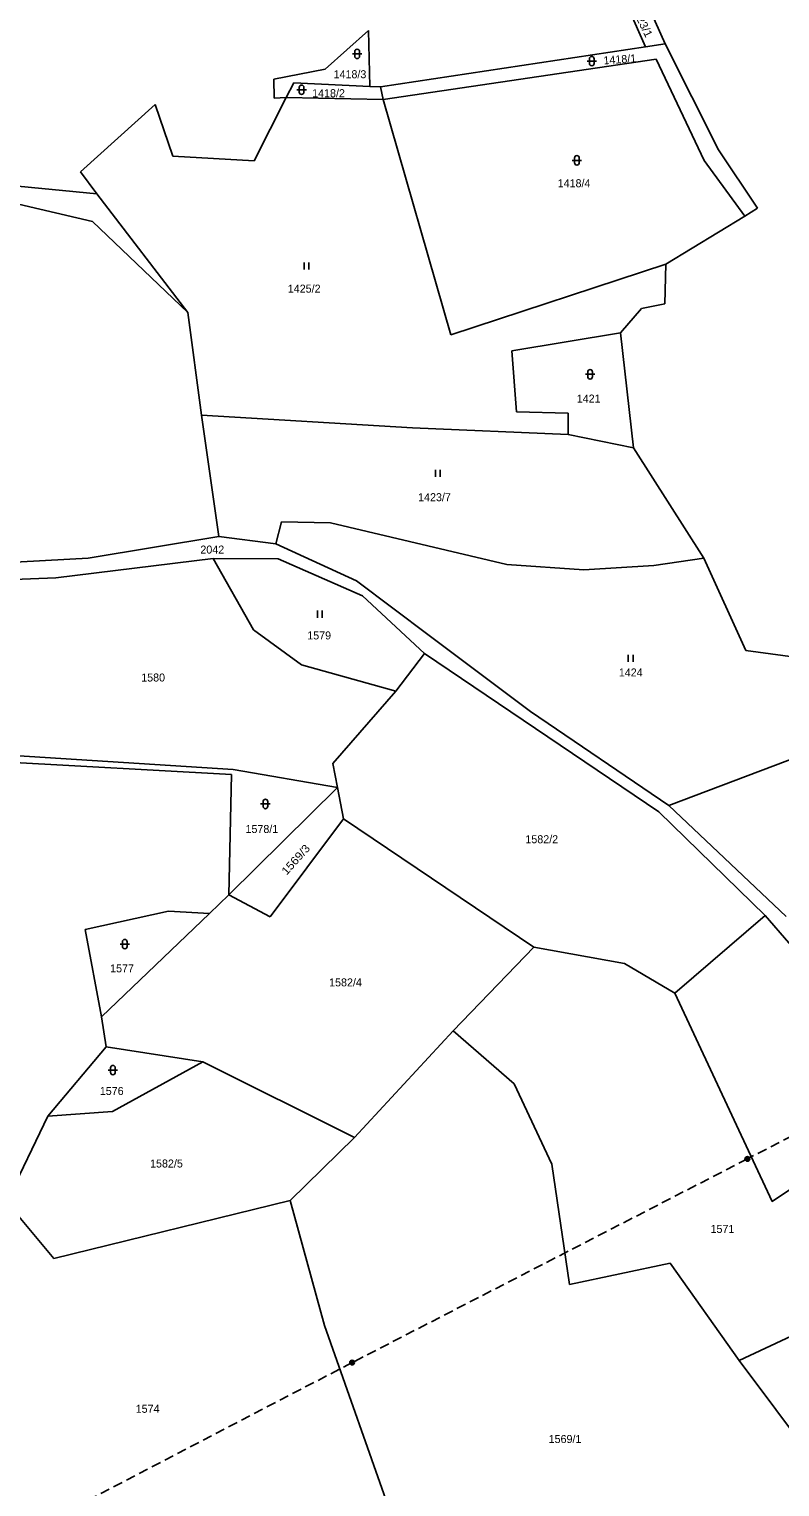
# Model space of a CAD drawing. Extents: x -820420 to -815896, y -1105820 to -1103643.
# Drawn here: x -819714.4 to -819555, y -1105122.1 to -1104812.4 of the extents above; entities that cross this region are included whole.
import ezdxf
from ezdxf.enums import TextEntityAlignment as Align

# ---------------------------------------------------------------- set-up
doc = ezdxf.new("R2010")
doc.units = 0
doc.header["$LTSCALE"] = 0.68
doc.linetypes.add('MEDIUM_DASHED', pattern=[4.5, 3, -1.5])
for name, color, linetype, lineweight in [('1', 7, 'Continuous', 25), ('3', 7, 'Continuous', 25), ('6', 7, 'Continuous', 25)]:
    doc.layers.add(name, color=color, linetype=linetype, lineweight=lineweight)
doc.layers.add('2', color=7, linetype='Continuous')

msp = doc.modelspace()

# ---------------------------------------------------------------- linework, layer by layer
at = {"layer": '1'}
for p, q in [((-819579.37, -1104815.59), (-819583.64, -1104806)), ((-819587.15, -1104808.04), (-819583.55, -1104816.2)), ((-819642.33, -1104812.74), (-819651.58, -1104820.92)), ((-819642.04, -1104824.65), (-819642.33, -1104812.74)), ((-819579.37, -1104815.59), (-819583.55, -1104816.2)), ((-819568.03, -1104838.09), (-819579.37, -1104815.59)), ((-819583.55, -1104816.2), (-819639.82, -1104824.69)), ((-819581.26, -1104818.83), (-819639.23, -1104827.35)), ((-819571.1, -1104840.38), (-819581.26, -1104818.83)), ((-819651.58, -1104820.92), (-819662.47, -1104823.07)), ((-819662.47, -1104823.07), (-819662.39, -1104827.12)), ((-819658.2, -1104823.82), (-819659.81, -1104826.98)), ((-819642.04, -1104824.65), (-819658.2, -1104823.82)), ((-819639.82, -1104824.69), (-819642.04, -1104824.65)), ((-819639.82, -1104824.69), (-819639.23, -1104827.35)), ((-819659.81, -1104826.98), (-819666.63, -1104840.44)), ((-819662.39, -1104827.12), (-819659.81, -1104826.98)), ((-819659.81, -1104826.98), (-819639.23, -1104827.35)), ((-819639.23, -1104827.35), (-819624.89, -1104877.35)), ((-819687.67, -1104828.45), (-819703.48, -1104842.74)), ((-819683.87, -1104839.45), (-819687.67, -1104828.45)), ((-819666.63, -1104840.44), (-819683.87, -1104839.45)), ((-819562.45, -1104852.17), (-819571.1, -1104840.38)), ((-819559.8, -1104850.47), (-819568.03, -1104838.09)), ((-819703.48, -1104842.74), (-819700.03, -1104847.45)), ((-819700.03, -1104847.45), (-819718.99, -1104845.59)), ((-819720, -1104848.84), (-819700.97, -1104853.31)), ((-819680.73, -1104872.66), (-819700.03, -1104847.45)), ((-819579.25, -1104862.38), (-819562.45, -1104852.17)), ((-819562.45, -1104852.17), (-819559.8, -1104850.47)), ((-819700.97, -1104853.31), (-819680.73, -1104872.66)), ((-819624.89, -1104877.35), (-819579.25, -1104862.38)), ((-819579.25, -1104862.38), (-819579.41, -1104870.8)), ((-819579.41, -1104870.8), (-819584.41, -1104871.8)), ((-819677.8, -1104894.43), (-819680.73, -1104872.66)), ((-819584.41, -1104871.8), (-819588.82, -1104876.95)), ((-819588.82, -1104876.95), (-819611.9, -1104880.79)), ((-819586.12, -1104901.36), (-819588.82, -1104876.95)), ((-819611.9, -1104880.79), (-819610.9, -1104893.76)), ((-819674.11, -1104920.23), (-819677.8, -1104894.43)), ((-819677.8, -1104894.43), (-819633.04, -1104897.15)), ((-819610.9, -1104893.76), (-819599.98, -1104894)), ((-819599.98, -1104894), (-819599.98, -1104898.54)), ((-819633.04, -1104897.15), (-819599.98, -1104898.54)), ((-819599.98, -1104898.54), (-819586.12, -1104901.36)), ((-819571.15, -1104924.83), (-819586.12, -1104901.36)), ((-819660.8, -1104917.11), (-819662.06, -1104921.79)), ((-819650.39, -1104917.34), (-819660.8, -1104917.11)), ((-819612.99, -1104926.2), (-819650.39, -1104917.34)), ((-819674.11, -1104920.23), (-819701.87, -1104924.82)), ((-819662.06, -1104921.79), (-819674.11, -1104920.23)), ((-819644.9, -1104929.62), (-819662.06, -1104921.79)), ((-819701.87, -1104924.82), (-819731.57, -1104926.45)), ((-819708.76, -1104928.99), (-819675.33, -1104924.89)), ((-819675.33, -1104924.89), (-819661.52, -1104925)), ((-819666.77, -1104940.09), (-819675.33, -1104924.89)), ((-819661.52, -1104925), (-819643.64, -1104932.8)), ((-819596.66, -1104927.28), (-819612.99, -1104926.2)), ((-819581.75, -1104926.4), (-819596.66, -1104927.28)), ((-819571.15, -1104924.83), (-819581.75, -1104926.4)), ((-819562.26, -1104944.46), (-819571.15, -1104924.83)), ((-819731.59, -1104929.93), (-819708.76, -1104928.99)), ((-819629.47, -1104941.24), (-819644.9, -1104929.62)), ((-819643.64, -1104932.8), (-819630.46, -1104945.08)), ((-819656.56, -1104947.49), (-819666.77, -1104940.09)), ((-819607.94, -1104957.4), (-819629.47, -1104941.24)), ((-819630.46, -1104945.08), (-819636.54, -1104953.09)), ((-819630.46, -1104945.08), (-819580.72, -1104978.73)), ((-819549.15, -1104946.25), (-819562.26, -1104944.46)), ((-819636.54, -1104953.09), (-819656.56, -1104947.49)), ((-819636.54, -1104953.09), (-819649.95, -1104968.42)), ((-819578.6, -1104977.35), (-819607.94, -1104957.4)), ((-819578.6, -1104977.35), (-819541.89, -1104963.48)), ((-819721.04, -1104966.54), (-819671.11, -1104969.73)), ((-819671.46, -1104970.78), (-819720.08, -1104968.12)), ((-819672.03, -1104996.33), (-819671.46, -1104970.78)), ((-819671.11, -1104969.73), (-819648.9, -1104973.56)), ((-819649.95, -1104968.42), (-819648.9, -1104973.56)), ((-819648.9, -1104973.56), (-819672.03, -1104996.33)), ((-819648.9, -1104973.56), (-819647.64, -1104980.21)), ((-819580.72, -1104978.73), (-819558.14, -1105000.72)), ((-819553.7, -1105000.95), (-819578.6, -1104977.35)), ((-819647.64, -1104980.21), (-819663.26, -1105001)), ((-819647.64, -1104980.21), (-819607.26, -1105007.49)), ((-819672.03, -1104996.33), (-819676.1, -1105000.31)), ((-819663.26, -1105001), (-819672.03, -1104996.33)), ((-819702.54, -1105003.71), (-819684.78, -1104999.8)), ((-819676.1, -1105000.31), (-819699.06, -1105022.31)), ((-819684.78, -1104999.8), (-819676.1, -1105000.31)), ((-819577.3, -1105017.24), (-819558.14, -1105000.72)), ((-819558.14, -1105000.72), (-819524.44, -1105039.84)), ((-819699.06, -1105022.31), (-819702.54, -1105003.71)), ((-819624.35, -1105025.26), (-819607.26, -1105007.49)), ((-819607.26, -1105007.49), (-819588.01, -1105010.94)), ((-819588.01, -1105010.94), (-819577.3, -1105017.24)), ((-819699.06, -1105022.31), (-819698.05, -1105028.63)), ((-819645.35, -1105047.88), (-819624.35, -1105025.26)), ((-819624.35, -1105025.26), (-819611.45, -1105036.51)), ((-819698.05, -1105028.63), (-819710.43, -1105043.35)), ((-819677.53, -1105031.84), (-819698.05, -1105028.63)), ((-819696.7, -1105042.37), (-819677.53, -1105031.84)), ((-819645.35, -1105047.88), (-819677.53, -1105031.84)), ((-819611.45, -1105036.51), (-819603.44, -1105053.6)), ((-819710.43, -1105043.35), (-819719, -1105061.23)), ((-819710.43, -1105043.35), (-819696.7, -1105042.37)), ((-819658.98, -1105061.27), (-819645.35, -1105047.88)), ((-819603.44, -1105053.6), (-819599.7, -1105079.17)), ((-819717.65, -1105063.44), (-819709.19, -1105073.62)), ((-819709.19, -1105073.62), (-819658.98, -1105061.27)), ((-819658.98, -1105061.27), (-819651.68, -1105087.83)), ((-819494, -1105062.46), (-819563.63, -1105095.3)), ((-819599.7, -1105079.17), (-819578.32, -1105074.6)), ((-819578.32, -1105074.6), (-819563.63, -1105095.3)), ((-819651.68, -1105087.83), (-819637.34, -1105128.66)), ((-819563.63, -1105095.3), (-819544.41, -1105121.09))]:
    msp.add_line(p, q, dxfattribs=at)
msp.add_lwpolyline([(-819577.3, -1105017.24), (-819556.63, -1105061.5), (-819524.44, -1105039.84)], dxfattribs=at)
at = {"layer": '3'}
for p, q in [((-819645.761, -1104817.701), (-819643.759, -1104817.701)), ((-819645.261, -1104817.201), (-819645.261, -1104818.202)), ((-819644.259, -1104818.202), (-819644.259, -1104817.201)), ((-819595.451, -1104818.721), (-819595.451, -1104819.722)), ((-819594.449, -1104819.722), (-819594.449, -1104818.721)), ((-819595.951, -1104819.221), (-819593.949, -1104819.221)), ((-819657.051, -1104824.821), (-819657.051, -1104825.822)), ((-819656.049, -1104825.822), (-819656.049, -1104824.821)), ((-819657.551, -1104825.321), (-819655.549, -1104825.321)), ((-819599.121, -1104840.311), (-819597.119, -1104840.311)), ((-819598.621, -1104839.811), (-819598.621, -1104840.812)), ((-819597.619, -1104840.812), (-819597.619, -1104839.811)), ((-819656.021, -1104863.52), (-819656.021, -1104862.02)), ((-819655.02, -1104863.52), (-819655.02, -1104862.02)), ((-819596.311, -1104885.771), (-819594.309, -1104885.771)), ((-819595.811, -1104885.271), (-819595.811, -1104886.272)), ((-819594.809, -1104886.272), (-819594.809, -1104885.271)), ((-819628.111, -1104907.57), (-819628.111, -1104906.07)), ((-819627.11, -1104907.57), (-819627.11, -1104906.07)), ((-819653.161, -1104937.48), (-819653.161, -1104935.98)), ((-819652.16, -1104937.48), (-819652.16, -1104935.98)), ((-819587.191, -1104946.84), (-819587.191, -1104945.34)), ((-819586.19, -1104946.84), (-819586.19, -1104945.34)), ((-819664.751, -1104976.551), (-819664.751, -1104977.552)), ((-819663.749, -1104977.552), (-819663.749, -1104976.551)), ((-819665.251, -1104977.051), (-819663.249, -1104977.051)), ((-819695.091, -1105006.831), (-819693.089, -1105006.831)), ((-819694.591, -1105006.331), (-819694.591, -1105007.332)), ((-819693.589, -1105007.332), (-819693.589, -1105006.331)), ((-819697.631, -1105033.581), (-819695.629, -1105033.581)), ((-819697.131, -1105033.081), (-819697.131, -1105034.082)), ((-819696.129, -1105034.082), (-819696.129, -1105033.081))]:
    msp.add_line(p, q, dxfattribs=at)
for centre, start, end in [((-819644.76, -1104817.2009), 0, 180), ((-819644.76, -1104818.2009), 180, 359.98789), ((-819594.95, -1104818.7209), 0, 180), ((-819594.95, -1104819.7209), 180, 359.98789), ((-819656.55, -1104824.8209), 0, 180), ((-819656.55, -1104825.8209), 180, 359.98789), ((-819598.12, -1104839.8109), 0, 180), ((-819598.12, -1104840.8109), 180, 359.98789), ((-819595.31, -1104885.2709), 0, 180), ((-819595.31, -1104886.2709), 180, 359.98789), ((-819664.25, -1104976.5509), 0, 180), ((-819664.25, -1104977.5509), 180, 359.98789), ((-819694.09, -1105006.3309), 0, 180), ((-819694.09, -1105007.3309), 180, 359.98789), ((-819696.63, -1105033.0809), 0, 180), ((-819696.63, -1105034.0809), 180, 359.98789)]:
    msp.add_arc(centre, 0.5, start, end, dxfattribs=at)
at = {"layer": '6', "linetype": 'MEDIUM_DASHED'}
for p, q in [((-819465.5, -1105002.47), (-819561.92, -1105052.46)), ((-819561.92, -1105052.46), (-819645.83, -1105095.73)), ((-819645.83, -1105095.73), (-819713.92, -1105131.23))]:
    msp.add_line(p, q, dxfattribs=at)
at = {"layer": '6'}
for centre, radius in [((-819561.9234, -1105052.4599), 0.5), ((-819561.9234, -1105052.4599), 0.4), ((-819561.9234, -1105052.4599), 0.3), ((-819561.9234, -1105052.4599), 0.2), ((-819561.9234, -1105052.4599), 0.1), ((-819645.8334, -1105095.7299), 0.5), ((-819645.8334, -1105095.7299), 0.4), ((-819645.8334, -1105095.7299), 0.3), ((-819645.8334, -1105095.7299), 0.2), ((-819645.8334, -1105095.7299), 0.1)]:
    msp.add_circle(centre, radius, dxfattribs=at)

# ---------------------------------------------------------------- texts
at = {"layer": '2'}
for s, rotation, width, p in [('1423/1', 296, 1.05, (-819585.0889, -1104811.0854)), ('1569/3', 48, 1.1, (-819657.1731, -1104989.4348))]:
    msp.add_text(s, height=1.7, rotation=rotation, dxfattribs=dict(at, width=width)).set_placement(p, align=Align.CENTER)
msp.add_text('1418/1', height=1.7, rotation=4, dxfattribs=at).set_placement((-819588.9398, -1104819.7011), align=Align.CENTER)
for s, p in [('1418/3', (-819646.29, -1104822.865)), ('1418/2', (-819650.84, -1104826.895)), ('1418/4', (-819598.71, -1104846.025)), ('1425/2', (-819656.01, -1104868.415)), ('1421', (-819595.61, -1104891.775)), ('1423/7', (-819628.34, -1104912.725)), ('2042', (-819675.52, -1104923.855)), ('1579', (-819652.83, -1104942.095)), ('1424', (-819586.68, -1104949.965)), ('1580', (-819688.08, -1104951.035)), ('1578/1', (-819664.99, -1104983.215)), ('1582/2', (-819605.57, -1104985.395)), ('1577', (-819694.68, -1105012.815)), ('1582/4', (-819647.24, -1105015.805)), ('1576', (-819696.87, -1105038.875)), ('1582/5', (-819685.25, -1105054.285)), ('1571', (-819567.21, -1105068.185)), ('1574', (-819689.25, -1105106.395)), ('1569/1', (-819600.63, -1105112.815))]:
    msp.add_text(s, height=1.7, dxfattribs=at).set_placement(p, align=Align.CENTER)

doc.saveas('drawing.dxf')
